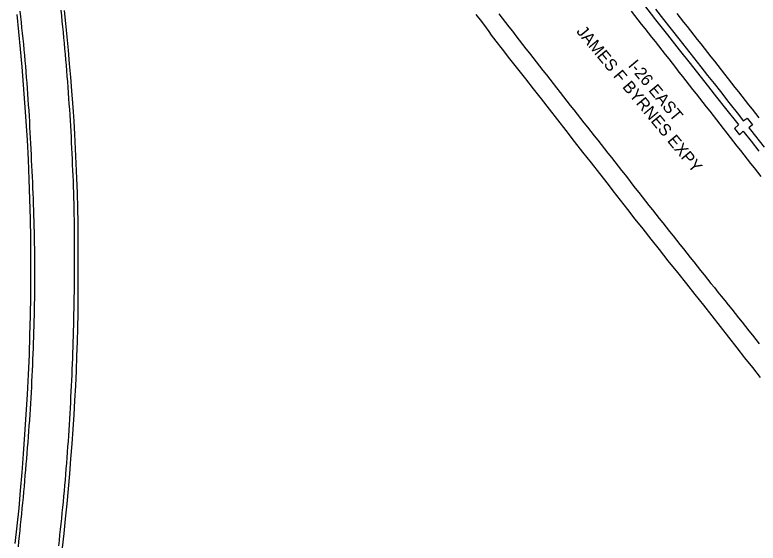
# Model space of a CAD drawing. Extents: x 1948091 to 1975253, y 787267 to 823306.
# Drawn here: x 1965675.4 to 1966011.2, y 802136.2 to 802374.8 of the extents above; entities that cross this region are included whole.
import ezdxf

# ---------------------------------------------------------------- set-up
doc = ezdxf.new("R2010")
doc.units = 0
for name, color, linetype in [('RD_EX_Pavement_Markings', 7, 'Continuous'), ('RD_EX_Road', 7, 'Continuous'), ('RD_TX_RoadID', 7, 'Continuous')]:
    doc.layers.add(name, color=color, linetype=linetype)

msp = doc.modelspace()

# ---------------------------------------------------------------- linework, layer by layer
at = {"layer": 'RD_EX_Pavement_Markings'}
for points in [[(1965677.68, 802376.46), (1965677.97, 802373.97), (1965678.25, 802371.49), (1965678.51, 802369), (1965678.78, 802366.52), (1965679.04, 802364.03), (1965679.3, 802361.55), (1965679.54, 802359.06), (1965679.77, 802356.57), (1965680, 802354.08), (1965680.22, 802351.59), (1965680.42, 802349.1), (1965680.62, 802346.6), (1965680.83, 802344.11), (1965681.03, 802341.62), (1965681.2, 802339.13), (1965681.36, 802336.63), (1965681.53, 802334.14), (1965681.7, 802331.64), (1965681.86, 802329.15), (1965681.99, 802326.65), (1965682.12, 802324.16), (1965682.25, 802321.66), (1965682.38, 802319.16), (1965682.51, 802316.67), (1965682.64, 802314.17), (1965682.77, 802311.67), (1965682.88, 802309.17), (1965683, 802306.68), (1965683.11, 802304.18), (1965683.23, 802301.68), (1965683.34, 802299.19), (1965683.46, 802296.69), (1965683.55, 802294.19), (1965683.64, 802291.69), (1965683.72, 802289.19), (1965683.81, 802286.69), (1965683.9, 802284.2), (1965683.98, 802281.7), (1965684.07, 802279.2), (1965684.12, 802276.7), (1965684.17, 802274.2), (1965684.22, 802271.7), (1965684.25, 802269.2), (1965684.28, 802266.7), (1965684.31, 802264.2), (1965684.34, 802261.7), (1965684.34, 802259.2), (1965684.35, 802256.7), (1965684.35, 802254.2), (1965684.33, 802251.7), (1965684.3, 802249.2), (1965684.27, 802246.7), (1965684.23, 802244.2), (1965684.17, 802241.7), (1965684.1, 802239.2), (1965684.04, 802236.7), (1965683.97, 802234.21), (1965683.89, 802231.71), (1965683.81, 802229.21), (1965683.74, 802226.71), (1965683.66, 802224.21), (1965683.56, 802221.71), (1965683.46, 802219.22), (1965683.35, 802216.72), (1965683.25, 802214.22), (1965683.15, 802211.72), (1965683.03, 802209.22), (1965682.91, 802206.73), (1965682.78, 802204.23), (1965682.65, 802201.73), (1965682.5, 802199.24), (1965682.33, 802196.75), (1965682.17, 802194.25), (1965682.01, 802191.76), (1965681.83, 802189.26), (1965681.63, 802186.77), (1965681.43, 802184.28), (1965681.24, 802181.79), (1965681.04, 802179.3), (1965680.84, 802176.8), (1965680.64, 802174.31), (1965680.43, 802171.82), (1965680.22, 802169.33), (1965680.01, 802166.84), (1965679.8, 802164.35), (1965679.59, 802161.86), (1965679.38, 802159.37), (1965679.14, 802156.88), (1965678.89, 802154.39), (1965678.64, 802151.9), (1965678.39, 802149.42), (1965678.13, 802146.93), (1965677.89, 802144.44), (1965677.64, 802141.96), (1965677.39, 802139.47), (1965677.14, 802136.98), (1965676.87, 802134.5)], [(1965695.31, 802134.95), (1965695.57, 802137.43), (1965695.83, 802139.92), (1965696.1, 802142.41), (1965696.36, 802144.89), (1965696.62, 802147.38), (1965696.87, 802149.87), (1965697.12, 802152.35), (1965697.37, 802154.84), (1965697.61, 802157.33), (1965697.86, 802159.82), (1965698.07, 802162.31), (1965698.27, 802164.8), (1965698.48, 802167.29), (1965698.68, 802169.78), (1965698.88, 802172.27), (1965699.07, 802174.76), (1965699.25, 802177.26), (1965699.43, 802179.75), (1965699.62, 802182.24), (1965699.79, 802184.74), (1965699.94, 802187.23), (1965700.1, 802189.73), (1965700.25, 802192.22), (1965700.4, 802194.72), (1965700.54, 802197.21), (1965700.67, 802199.71), (1965700.8, 802202.21), (1965700.93, 802204.7), (1965701.06, 802207.2), (1965701.17, 802209.7), (1965701.27, 802212.2), (1965701.38, 802214.69), (1965701.48, 802217.19), (1965701.59, 802219.69), (1965701.67, 802222.19), (1965701.75, 802224.69), (1965701.82, 802227.18), (1965701.9, 802229.68), (1965701.98, 802232.18), (1965702.04, 802234.68), (1965702.09, 802237.18), (1965702.15, 802239.68), (1965702.2, 802242.18), (1965702.26, 802244.68), (1965702.29, 802247.18), (1965702.32, 802249.68), (1965702.35, 802252.18), (1965702.38, 802254.68), (1965702.4, 802257.18), (1965702.41, 802259.68), (1965702.42, 802262.18), (1965702.42, 802264.68), (1965702.43, 802267.18), (1965702.43, 802269.68), (1965702.41, 802272.18), (1965702.39, 802274.68), (1965702.36, 802277.18), (1965702.34, 802279.68), (1965702.32, 802282.18), (1965702.28, 802284.68), (1965702.22, 802287.18), (1965702.17, 802289.68), (1965702.12, 802292.18), (1965702.06, 802294.67), (1965701.96, 802297.17), (1965701.86, 802299.67), (1965701.75, 802302.17), (1965701.65, 802304.67), (1965701.54, 802307.16), (1965701.43, 802309.66), (1965701.32, 802312.16), (1965701.2, 802314.66), (1965701.08, 802317.15), (1965700.97, 802319.65), (1965700.85, 802322.15), (1965700.7, 802324.64), (1965700.54, 802327.14), (1965700.38, 802329.63), (1965700.21, 802332.13), (1965700.05, 802334.62), (1965699.87, 802337.12), (1965699.69, 802339.61), (1965699.5, 802342.1), (1965699.32, 802344.6), (1965699.13, 802347.09), (1965698.92, 802349.58), (1965698.71, 802352.07), (1965698.5, 802354.56), (1965698.29, 802357.05), (1965698.07, 802359.54), (1965697.83, 802362.03), (1965697.59, 802364.52), (1965697.36, 802367.01), (1965697.12, 802369.5), (1965696.87, 802371.99), (1965696.6, 802374.47), (1965696.33, 802376.96)], [(1965894.02, 802375.27), (1965895.56, 802373.31), (1965897.1, 802371.34), (1965898.64, 802369.37), (1965900.18, 802367.4), (1965901.72, 802365.43), (1965903.26, 802363.46), (1965904.79, 802361.49), (1965906.33, 802359.53), (1965907.87, 802357.56), (1965909.41, 802355.59), (1965910.95, 802353.62), (1965912.48, 802351.65), (1965914.02, 802349.68), (1965915.56, 802347.71), (1965917.1, 802345.74), (1965918.64, 802343.77), (1965920.18, 802341.8), (1965921.71, 802339.83), (1965923.26, 802337.87), (1965924.81, 802335.91), (1965926.35, 802333.94), (1965927.9, 802331.98), (1965929.45, 802330.02), (1965931, 802328.06), (1965932.54, 802326.1), (1965934.09, 802324.13), (1965935.64, 802322.17), (1965937.19, 802320.21), (1965938.73, 802318.25), (1965940.28, 802316.28), (1965941.83, 802314.32), (1965943.37, 802312.36), (1965944.91, 802310.39), (1965946.45, 802308.42), (1965947.99, 802306.45), (1965949.54, 802304.49), (1965951.08, 802302.52), (1965952.62, 802300.55), (1965954.16, 802298.58), (1965955.7, 802296.62), (1965957.24, 802294.65), (1965958.78, 802292.68), (1965960.32, 802290.72), (1965961.87, 802288.75), (1965963.43, 802286.8), (1965964.98, 802284.84), (1965966.54, 802282.89), (1965968.09, 802280.93), (1965969.65, 802278.97), (1965971.21, 802277.02), (1965972.76, 802275.06), (1965974.32, 802273.11), (1965975.88, 802271.15), (1965977.43, 802269.2), (1965978.99, 802267.24), (1965980.55, 802265.29), (1965982.1, 802263.33), (1965983.66, 802261.38), (1965985.22, 802259.42), (1965986.77, 802257.47), (1965988.33, 802255.51), (1965989.89, 802253.56), (1965991.45, 802251.61), (1965993.01, 802249.65), (1965994.57, 802247.7), (1965996.13, 802245.75), (1965997.69, 802243.8), (1965999.25, 802241.84), (1966000.81, 802239.89), (1966002.37, 802237.94), (1966003.93, 802235.99), (1966005.49, 802234.03), (1966007.05, 802232.08), (1966008.61, 802230.13), (1966010.17, 802228.17), (1966011.73, 802226.22)], [(1965953.78, 802376.49), (1965955.33, 802374.53), (1965956.88, 802372.57), (1965958.43, 802370.61), (1965959.98, 802368.64), (1965961.53, 802366.68), (1965963.08, 802364.72), (1965964.63, 802362.76), (1965966.18, 802360.8), (1965967.73, 802358.84), (1965969.28, 802356.88), (1965970.82, 802354.92), (1965972.36, 802352.95), (1965973.91, 802350.99), (1965975.45, 802349.02), (1965977, 802347.06), (1965978.54, 802345.09), (1965980.09, 802343.13), (1965981.63, 802341.16), (1965983.18, 802339.2), (1965984.72, 802337.23), (1965986.25, 802335.26), (1965987.79, 802333.29), (1965989.33, 802331.32), (1965990.86, 802329.35), (1965992.4, 802327.38), (1965993.94, 802325.41), (1965995.48, 802323.44), (1965997.01, 802321.47), (1965998.55, 802319.5), (1966000.09, 802317.53), (1966001.63, 802315.56), (1966003.18, 802313.6), (1966004.72, 802311.64), (1966006.27, 802309.67), (1966007.82, 802307.71), (1966009.36, 802305.75), (1966010.91, 802303.78), (1966012.46, 802301.82)], [(1965974.45, 802375.47), (1965975.99, 802373.51), (1965977.54, 802371.54), (1965979.08, 802369.58), (1965980.63, 802367.62), (1965982.17, 802365.65), (1965983.72, 802363.69), (1965985.26, 802361.72), (1965986.81, 802359.76), (1965988.35, 802357.8), (1965989.9, 802355.83), (1965991.45, 802353.87), (1965992.99, 802351.9), (1965994.54, 802349.94), (1965996.08, 802347.98), (1965997.63, 802346.01), (1965999.17, 802344.05), (1966000.72, 802342.08), (1966002.26, 802340.12), (1966003.81, 802338.15), (1966005.35, 802336.19), (1966006.9, 802334.23), (1966008.44, 802332.26), (1966009.99, 802330.3), (1966011.53, 802328.33)]]:
    msp.add_lwpolyline(points, dxfattribs=at)
at = {"layer": 'RD_EX_Road'}
for points in [[(1965959.36, 802379.61), (1965964.89, 802372.62), (1965970.27, 802365.8), (1965975.53, 802359.11), (1965980.46, 802352.84), (1965984.82, 802347.31), (1965988.75, 802342.34), (1965992.37, 802337.73), (1965996.51, 802332.47), (1966002, 802325.54), (1966002.29, 802325.16), (1966000.5, 802323.57), (1966002.82, 802320.63), (1966004.49, 802322.28), (1966004.96, 802321.67), (1966007.99, 802317.82), (1966011.59, 802313.27)], [(1965964.84, 802377.38), (1965968.44, 802372.81), (1965971.93, 802368.36), (1965975.33, 802364.04), (1965978.68, 802359.77), (1965982.05, 802355.5), (1965985.33, 802351.35), (1965988.4, 802347.47), (1965991.32, 802343.77), (1965994.15, 802340.19), (1965998.01, 802335.28), (1966002.26, 802329.86), (1966004.03, 802327.61), (1966004.48, 802327.04), (1966006.24, 802328.16), (1966008.62, 802325.16), (1966007.02, 802323.86), (1966007.77, 802322.92), (1966013.88, 802315.08)], [(1965676.27, 802374.99), (1965677.09, 802367.15), (1965677.88, 802359.3), (1965678.61, 802351.37), (1965679.27, 802343.29), (1965679.87, 802335.08), (1965680.44, 802326.76), (1965680.96, 802318.23), (1965681.42, 802309.43), (1965681.81, 802300.51), (1965682.11, 802291.59), (1965682.32, 802282.7), (1965682.46, 802273.83), (1965682.51, 802265.04), (1965682.5, 802256.39), (1965682.44, 802247.74), (1965682.32, 802238.94), (1965682.13, 802230.08), (1965681.85, 802221.23), (1965681.48, 802212.33), (1965681, 802203.34), (1965680.44, 802194.31), (1965679.81, 802185.29), (1965679.16, 802176.48), (1965678.54, 802168.08), (1965677.9, 802159.97), (1965677.17, 802152), (1965676.36, 802144.06), (1965675.45, 802135.99)], [(1965696.98, 802134.05), (1965697.72, 802140.64), (1965698.39, 802147.26), (1965699.02, 802153.94), (1965699.64, 802160.72), (1965700.23, 802167.54), (1965700.78, 802174.35), (1965701.29, 802181.09), (1965701.76, 802187.67), (1965702.19, 802194.17), (1965702.57, 802200.67), (1965702.92, 802207.25), (1965703.24, 802213.97), (1965703.51, 802220.65), (1965703.72, 802227.07), (1965703.87, 802233.45), (1965703.99, 802239.95), (1965704.08, 802246.6), (1965704.11, 802253.4), (1965704.11, 802260.27), (1965704.1, 802267.13), (1965704.07, 802273.98), (1965703.99, 802280.84), (1965703.87, 802287.65), (1965703.7, 802294.35), (1965703.47, 802301), (1965703.18, 802307.68), (1965702.85, 802314.36), (1965702.5, 802321.01), (1965702.18, 802326.82), (1965701.92, 802330.98), (1965701.62, 802335.02), (1965701.19, 802340.47), (1965700.69, 802346.62), (1965700.16, 802352.73), (1965699.63, 802358.83), (1965699.06, 802364.92), (1965698.48, 802370.93), (1965697.87, 802376.82)], [(1965883.7, 802374.93), (1965886.2, 802371.77), (1965888.3, 802369.01), (1965889.48, 802367.36), (1965890.66, 802365.72), (1965892.73, 802362.97), (1965895.54, 802359.33), (1965898.9, 802355.02), (1965902.51, 802350.44), (1965906.06, 802345.96), (1965909.6, 802341.47), (1965913.19, 802336.88), (1965916.85, 802332.18), (1965920.58, 802327.38), (1965924.36, 802322.54), (1965928.14, 802317.7), (1965931.94, 802312.86), (1965935.74, 802308.02), (1965939.56, 802303.15), (1965943.42, 802298.18), (1965945.62, 802295.34), (1965948.89, 802291.13), (1965952.21, 802286.9), (1965955.58, 802282.61), (1965959.05, 802278.19), (1965962.66, 802273.59), (1965966.44, 802268.78), (1965970.48, 802263.73), (1965974.72, 802258.48), (1965978.8, 802253.41), (1965982.67, 802248.56), (1965986.48, 802243.73), (1965990.27, 802238.89), (1965994.07, 802234.03), (1965997.88, 802229.18), (1966001.55, 802224.49), (1966005.08, 802219.98), (1966008.59, 802215.49), (1966012.09, 802211)]]:
    msp.add_lwpolyline(points, dxfattribs=at)

# ---------------------------------------------------------------- texts
at = {"layer": 'RD_TX_RoadID'}
for s, p in [('JAMES F BYRNES EXPY', (1965928.81, 802367.21)), ('I-26 EAST', (1965952.18, 802351.8))]:
    msp.add_text(s, height=5.4, rotation=309.7715, dxfattribs=at).set_placement(p)

doc.saveas('drawing.dxf')
